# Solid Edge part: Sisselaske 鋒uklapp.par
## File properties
Author: Türk
Template: Iso Part.par
Last saved by: Türk
Revision: 5
Application: Solid Edge
Accuracy: 0,990
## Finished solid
Body 1: solid body, 63 faces, 136 edges, 72 vertices.
  Faces by surface: cylinder 27, plane 16, torus 12, sphere 7, cone 1
  Edges by curve: circle 72, line 61, intersection 2, ellipse 1
Bounding box of the edges (mm; curved faces can reach further): 120.000 x 56.000 x 139.000, from (-60, -46, -67.5) to (60, 10, 71.5).
Cylindrical faces by radius (mm): R0.5 x16, R4 x4, R5 x2, R40 x1, R47.5 x1, R50 x1, R60 x2
Conical faces (half-angle, radius in mm at the cone's reference point): 45 deg R55 x1
Toroidal faces (ring radius, tube radius in mm): R0.5 r0.5 x8, R59.5 r0.5 x4
Spherical faces by radius (mm): R0.5 x7
Planar faces by outward normal: +x 3, +y 3, +z 2, -x 2, -y 2, -z 3, oblique 1
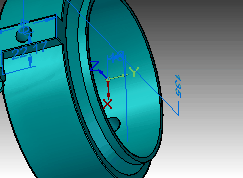
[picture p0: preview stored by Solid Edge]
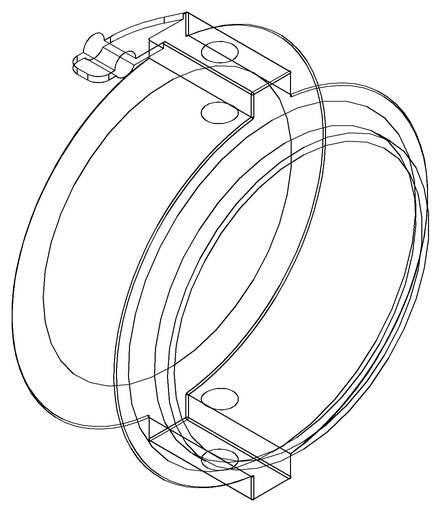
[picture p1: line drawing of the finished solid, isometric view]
